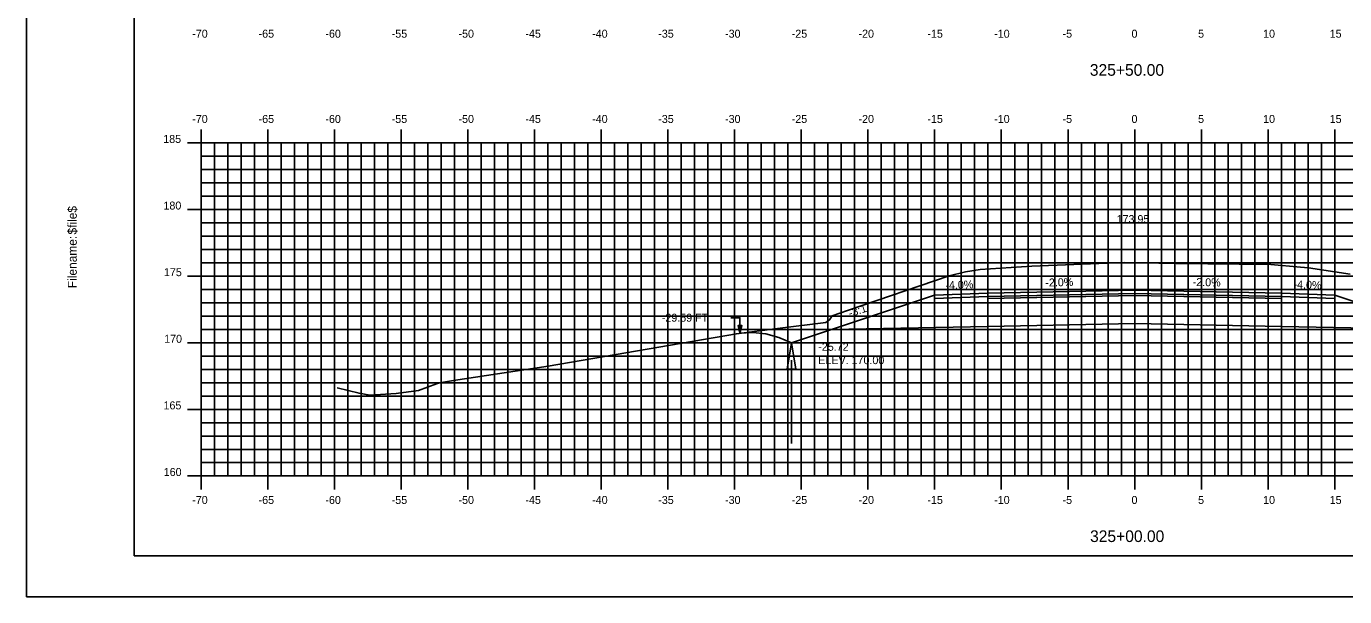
# Model space of a CAD drawing. Extents: x 1140537 to 1140707, y 608981 to 609091.
# Drawn here: x 1140537.2 to 1140636, y 608981.3 to 609024.1 of the extents above; entities that cross this region are included whole.
import ezdxf

# ---------------------------------------------------------------- set-up
doc = ezdxf.new("R2010")
doc.units = 0
for name, color, linetype in [('ANNOTATION', 7, 'Continuous'), ('BORDER', 7, 'Continuous'), ('D_Drainage_Ditch_Line', 7, 'Continuous'), ('D_Roadway_Centerline', 7, 'Continuous'), ('D_Roadway_Centerline_Text', 7, 'Continuous'), ('D_Roadway_Edge_Shoulder', 7, 'Continuous'), ('D_Roadway_Edge_TW', 7, 'Continuous'), ('D_Roadway_Pavement', 7, 'Continuous'), ('D_Roadway_SlopeLines', 7, 'Continuous'), ('D_Roadway_SubGrade', 7, 'Continuous'), ('D_Text_Standard', 7, 'Continuous'), ('H_V ANNOTATION', 7, 'Continuous'), ('MAJOR', 7, 'Continuous'), ('MINOR', 7, 'Continuous'), ('PLOT BOUNDARY', 7, 'Continuous'), ('S_Roadway_Centerline', 7, 'Continuous')]:
    doc.layers.add(name, color=color, linetype=linetype)

msp = doc.modelspace()

# ---------------------------------------------------------------- linework, layer by layer
msp.add_lwpolyline([(1140590.652, 609001.047), (1140591.619, 609001.097), (1140592.586, 609000.995), (1140593.553, 609000.74), (1140594.52, 609000.333), (1140597.52, 609001.333), (1140605.244, 609003.907), (1140605.245, 609003.907), (1140609.245, 609004.067), (1140620.245, 609004.287), (1140631.245, 609004.067), (1140635.245, 609003.907), (1140642.968, 609001.333), (1140645.968, 609000.333), (1140654.069, 609004.383), (1140655.319, 609004.932), (1140656.569, 609005.328), (1140657.819, 609005.571), (1140659.069, 609005.661)])
at = {"layer": 'BORDER'}
msp.add_lwpolyline([(1140545.245, 608984.335), (1140705.245, 608984.335), (1140705.245, 609089.335), (1140545.245, 609089.335)], close=True, dxfattribs=at)
at = {"layer": 'D_Drainage_Ditch_Line'}
msp.add_line((1140594.52, 608999.021), (1140594.52, 608992.777), dxfattribs=at)
msp.add_lwpolyline([(1140594.848, 608998.364), (1140594.192, 608998.364), (1140594.52, 609000.333)], close=True, dxfattribs=at)
at = {"layer": 'D_Roadway_Edge_Shoulder'}
for points in [[(1140609.245, 609004.067), (1140605.245, 609003.907), (1140605.245, 609003.657), (1140609.245, 609003.817)], [(1140631.245, 609004.067), (1140635.245, 609003.907), (1140635.245, 609003.657), (1140631.245, 609003.817)]]:
    msp.add_lwpolyline(points, close=True, dxfattribs=at)
at = {"layer": 'D_Roadway_Edge_TW'}
msp.add_lwpolyline([(1140609.245, 609003.817), (1140609.245, 609004.067), (1140620.245, 609004.287), (1140631.245, 609004.067), (1140631.245, 609003.817), (1140620.245, 609004.037)], close=True, dxfattribs=at)
at = {"layer": 'D_Roadway_Pavement'}
msp.add_lwpolyline([(1140609.245, 609003.651), (1140609.245, 609003.817), (1140620.245, 609004.037), (1140631.245, 609003.817), (1140631.245, 609003.651), (1140620.245, 609003.871)], close=True, dxfattribs=at)
at = {"layer": 'D_Roadway_SlopeLines'}
for points in [[(1140594.52, 609000.333), (1140593.553, 609000.74), (1140592.586, 609000.995), (1140591.619, 609001.097), (1140590.652, 609001.047)], [(1140597.52, 609001.333), (1140594.52, 609000.333)]]:
    msp.add_lwpolyline(points, dxfattribs=at)
at = {"layer": 'D_Roadway_SubGrade'}
for points in [[(1140609.245, 609003.651), (1140609.245, 609003.817), (1140605.245, 609003.657), (1140605.245, 609003.907), (1140605.244, 609003.907), (1140597.52, 609001.333), (1140609.245, 609001.567)], [(1140609.245, 609001.567), (1140609.245, 609003.651), (1140620.245, 609003.871), (1140631.245, 609003.651), (1140631.245, 609001.567), (1140620.245, 609001.787)], [(1140631.245, 609003.651), (1140631.245, 609003.817), (1140635.245, 609003.657), (1140635.245, 609003.907), (1140635.245, 609003.907), (1140642.968, 609001.333), (1140631.245, 609001.567)]]:
    msp.add_lwpolyline(points, close=True, dxfattribs=at)
at = {"layer": 'D_Text_Standard'}
msp.add_lwpolyline([(1140590.652, 609001.047), (1140590.648, 609002.216), (1140589.968, 609002.216)], dxfattribs=at)
msp.add_lwpolyline([(1140590.652, 609001.047), (1140590.504, 609001.628), (1140590.796, 609001.629)], close=True, dxfattribs=at)
at = {"layer": 'MAJOR'}
for p, q in [((1140550.245, 609016.337), (1140550.245, 609015.335)), ((1140555.245, 609016.337), (1140555.245, 609015.335)), ((1140560.245, 609016.337), (1140560.245, 609015.335)), ((1140565.245, 609016.337), (1140565.245, 609015.335)), ((1140570.245, 609016.337), (1140570.245, 609015.335)), ((1140575.245, 609016.337), (1140575.245, 609015.335)), ((1140580.245, 609016.337), (1140580.245, 609015.335)), ((1140585.245, 609016.337), (1140585.245, 609015.335)), ((1140590.245, 609016.337), (1140590.245, 609015.335)), ((1140595.245, 609016.337), (1140595.245, 609015.335)), ((1140600.245, 609016.337), (1140600.245, 609015.335)), ((1140605.245, 609016.337), (1140605.245, 609015.335)), ((1140610.245, 609016.337), (1140610.245, 609015.335)), ((1140615.245, 609016.337), (1140615.245, 609015.335)), ((1140620.245, 609016.337), (1140620.245, 609015.335)), ((1140625.245, 609016.337), (1140625.245, 609015.335)), ((1140630.245, 609016.337), (1140630.245, 609015.335)), ((1140635.245, 609016.337), (1140635.245, 609015.335)), ((1140549.243, 609015.335), (1140550.245, 609015.335)), ((1140550.245, 609015.335), (1140690.245, 609015.335)), ((1140550.245, 608990.335), (1140550.245, 609015.335)), ((1140550.245, 608990.335), (1140550.245, 609015.335)), ((1140550.245, 609015.335), (1140690.245, 609015.335)), ((1140555.245, 608990.335), (1140555.245, 609015.335)), ((1140560.245, 608990.335), (1140560.245, 609015.335)), ((1140565.245, 608990.335), (1140565.245, 609015.335)), ((1140570.245, 608990.335), (1140570.245, 609015.335)), ((1140575.245, 608990.335), (1140575.245, 609015.335)), ((1140580.245, 608990.335), (1140580.245, 609015.335)), ((1140585.245, 608990.335), (1140585.245, 609015.335)), ((1140590.245, 608990.335), (1140590.245, 609015.335)), ((1140595.245, 608990.335), (1140595.245, 609015.335)), ((1140600.245, 608990.335), (1140600.245, 609015.335)), ((1140605.245, 608990.335), (1140605.245, 609015.335)), ((1140610.245, 608990.335), (1140610.245, 609015.335)), ((1140615.245, 608990.335), (1140615.245, 609015.335)), ((1140620.245, 608990.335), (1140620.245, 609015.335)), ((1140625.245, 608990.335), (1140625.245, 609015.335)), ((1140630.245, 608990.335), (1140630.245, 609015.335)), ((1140635.245, 608990.335), (1140635.245, 609015.335)), ((1140549.243, 609010.335), (1140550.245, 609010.335)), ((1140550.245, 609010.335), (1140690.245, 609010.335)), ((1140549.243, 609005.335), (1140550.245, 609005.335)), ((1140550.245, 609005.335), (1140690.245, 609005.335)), ((1140549.243, 609000.335), (1140550.245, 609000.335)), ((1140550.245, 609000.335), (1140690.245, 609000.335)), ((1140549.243, 608995.335), (1140550.245, 608995.335)), ((1140550.245, 608995.335), (1140690.245, 608995.335)), ((1140549.243, 608990.335), (1140550.245, 608990.335)), ((1140550.245, 608990.335), (1140690.245, 608990.335)), ((1140550.245, 608990.335), (1140690.245, 608990.335)), ((1140550.245, 608989.333), (1140550.245, 608990.335)), ((1140555.245, 608989.333), (1140555.245, 608990.335)), ((1140560.245, 608989.333), (1140560.245, 608990.335)), ((1140565.245, 608989.333), (1140565.245, 608990.335)), ((1140570.245, 608989.333), (1140570.245, 608990.335)), ((1140575.245, 608989.333), (1140575.245, 608990.335)), ((1140580.245, 608989.333), (1140580.245, 608990.335)), ((1140585.245, 608989.333), (1140585.245, 608990.335)), ((1140590.245, 608989.333), (1140590.245, 608990.335)), ((1140595.245, 608989.333), (1140595.245, 608990.335)), ((1140600.245, 608989.333), (1140600.245, 608990.335)), ((1140605.245, 608989.333), (1140605.245, 608990.335)), ((1140610.245, 608989.333), (1140610.245, 608990.335)), ((1140615.245, 608989.333), (1140615.245, 608990.335)), ((1140620.245, 608989.333), (1140620.245, 608990.335)), ((1140625.245, 608989.333), (1140625.245, 608990.335)), ((1140630.245, 608989.333), (1140630.245, 608990.335)), ((1140635.245, 608989.333), (1140635.245, 608990.335))]:
    msp.add_line(p, q, dxfattribs=at)
at = {"layer": 'MINOR'}
for p, q in [((1140551.245, 608990.335), (1140551.245, 609015.335)), ((1140552.245, 608990.335), (1140552.245, 609015.335)), ((1140553.245, 608990.335), (1140553.245, 609015.335)), ((1140554.245, 608990.335), (1140554.245, 609015.335)), ((1140556.245, 608990.335), (1140556.245, 609015.335)), ((1140557.245, 608990.335), (1140557.245, 609015.335)), ((1140558.245, 608990.335), (1140558.245, 609015.335)), ((1140559.245, 608990.335), (1140559.245, 609015.335)), ((1140561.245, 608990.335), (1140561.245, 609015.335)), ((1140562.245, 608990.335), (1140562.245, 609015.335)), ((1140563.245, 608990.335), (1140563.245, 609015.335)), ((1140564.245, 608990.335), (1140564.245, 609015.335)), ((1140566.245, 608990.335), (1140566.245, 609015.335)), ((1140567.245, 608990.335), (1140567.245, 609015.335)), ((1140568.245, 608990.335), (1140568.245, 609015.335)), ((1140569.245, 608990.335), (1140569.245, 609015.335)), ((1140571.245, 608990.335), (1140571.245, 609015.335)), ((1140572.245, 608990.335), (1140572.245, 609015.335)), ((1140573.245, 608990.335), (1140573.245, 609015.335)), ((1140574.245, 608990.335), (1140574.245, 609015.335)), ((1140576.245, 608990.335), (1140576.245, 609015.335)), ((1140577.245, 608990.335), (1140577.245, 609015.335)), ((1140578.245, 608990.335), (1140578.245, 609015.335)), ((1140579.245, 608990.335), (1140579.245, 609015.335)), ((1140581.245, 608990.335), (1140581.245, 609015.335)), ((1140582.245, 608990.335), (1140582.245, 609015.335)), ((1140583.245, 608990.335), (1140583.245, 609015.335)), ((1140584.245, 608990.335), (1140584.245, 609015.335)), ((1140586.245, 608990.335), (1140586.245, 609015.335)), ((1140587.245, 608990.335), (1140587.245, 609015.335)), ((1140588.245, 608990.335), (1140588.245, 609015.335)), ((1140589.245, 608990.335), (1140589.245, 609015.335)), ((1140591.245, 608990.335), (1140591.245, 609015.335)), ((1140592.245, 608990.335), (1140592.245, 609015.335)), ((1140593.245, 608990.335), (1140593.245, 609015.335)), ((1140594.245, 608990.335), (1140594.245, 609015.335)), ((1140596.245, 608990.335), (1140596.245, 609015.335)), ((1140597.245, 608990.335), (1140597.245, 609015.335)), ((1140598.245, 608990.335), (1140598.245, 609015.335)), ((1140599.245, 608990.335), (1140599.245, 609015.335)), ((1140601.245, 608990.335), (1140601.245, 609015.335)), ((1140602.245, 608990.335), (1140602.245, 609015.335)), ((1140603.245, 608990.335), (1140603.245, 609015.335)), ((1140604.245, 608990.335), (1140604.245, 609015.335)), ((1140606.245, 608990.335), (1140606.245, 609015.335)), ((1140607.245, 608990.335), (1140607.245, 609015.335)), ((1140608.245, 608990.335), (1140608.245, 609015.335)), ((1140609.245, 608990.335), (1140609.245, 609015.335)), ((1140611.245, 608990.335), (1140611.245, 609015.335)), ((1140612.245, 608990.335), (1140612.245, 609015.335)), ((1140613.245, 608990.335), (1140613.245, 609015.335)), ((1140614.245, 608990.335), (1140614.245, 609015.335)), ((1140616.245, 608990.335), (1140616.245, 609015.335)), ((1140617.245, 608990.335), (1140617.245, 609015.335)), ((1140618.245, 608990.335), (1140618.245, 609015.335)), ((1140619.245, 608990.335), (1140619.245, 609015.335)), ((1140621.245, 608990.335), (1140621.245, 609015.335)), ((1140622.245, 608990.335), (1140622.245, 609015.335)), ((1140623.245, 608990.335), (1140623.245, 609015.335)), ((1140624.245, 608990.335), (1140624.245, 609015.335)), ((1140626.245, 608990.335), (1140626.245, 609015.335)), ((1140627.245, 608990.335), (1140627.245, 609015.335)), ((1140628.245, 608990.335), (1140628.245, 609015.335)), ((1140629.245, 608990.335), (1140629.245, 609015.335)), ((1140631.245, 608990.335), (1140631.245, 609015.335)), ((1140632.245, 608990.335), (1140632.245, 609015.335)), ((1140633.245, 608990.335), (1140633.245, 609015.335)), ((1140634.245, 608990.335), (1140634.245, 609015.335)), ((1140550.245, 609014.335), (1140690.245, 609014.335)), ((1140550.245, 609014.335), (1140551.247, 609014.335)), ((1140550.245, 609013.335), (1140690.245, 609013.335)), ((1140550.245, 609013.335), (1140551.247, 609013.335)), ((1140550.245, 609012.335), (1140690.245, 609012.335)), ((1140550.245, 609012.335), (1140551.247, 609012.335)), ((1140550.245, 609011.335), (1140690.245, 609011.335)), ((1140550.245, 609011.335), (1140551.247, 609011.335)), ((1140550.245, 609009.335), (1140690.245, 609009.335)), ((1140550.245, 609009.335), (1140551.247, 609009.335)), ((1140550.245, 609008.335), (1140690.245, 609008.335)), ((1140550.245, 609008.335), (1140551.247, 609008.335)), ((1140550.245, 609007.335), (1140690.245, 609007.335)), ((1140550.245, 609007.335), (1140551.247, 609007.335)), ((1140550.245, 609006.335), (1140690.245, 609006.335)), ((1140550.245, 609006.335), (1140551.247, 609006.335)), ((1140550.245, 609004.335), (1140690.245, 609004.335)), ((1140550.245, 609004.335), (1140551.247, 609004.335)), ((1140550.245, 609003.335), (1140690.245, 609003.335)), ((1140550.245, 609003.335), (1140551.247, 609003.335)), ((1140550.245, 609002.335), (1140690.245, 609002.335)), ((1140550.245, 609002.335), (1140551.247, 609002.335)), ((1140550.245, 609001.335), (1140690.245, 609001.335)), ((1140550.245, 609001.335), (1140551.247, 609001.335)), ((1140550.245, 608999.335), (1140690.245, 608999.335)), ((1140550.245, 608999.335), (1140551.247, 608999.335)), ((1140550.245, 608998.335), (1140690.245, 608998.335)), ((1140550.245, 608998.335), (1140551.247, 608998.335)), ((1140550.245, 608997.335), (1140690.245, 608997.335)), ((1140550.245, 608997.335), (1140551.247, 608997.335)), ((1140550.245, 608996.335), (1140690.245, 608996.335)), ((1140550.245, 608996.335), (1140551.247, 608996.335)), ((1140550.245, 608994.335), (1140690.245, 608994.335)), ((1140550.245, 608994.335), (1140551.247, 608994.335)), ((1140550.245, 608993.335), (1140690.245, 608993.335)), ((1140550.245, 608993.335), (1140551.247, 608993.335)), ((1140550.245, 608992.335), (1140690.245, 608992.335)), ((1140550.245, 608992.335), (1140551.247, 608992.335)), ((1140550.245, 608991.335), (1140690.245, 608991.335)), ((1140550.245, 608991.335), (1140551.247, 608991.335))]:
    msp.add_line(p, q, dxfattribs=at)
at = {"layer": 'PLOT BOUNDARY'}
msp.add_lwpolyline([(1140537.151, 608981.276), (1140707.151, 608981.276), (1140707.151, 609091.276), (1140537.151, 609091.276)], close=True, dxfattribs=at)
at = {"layer": 'S_Roadway_Centerline'}
msp.add_lwpolyline([(1140560.445, 608996.953), (1140562.096, 608996.55), (1140562.911, 608996.409), (1140564.877, 608996.526), (1140566.549, 608996.741), (1140567.911, 608997.253), (1140568.116, 608997.339), (1140569.162, 608997.501), (1140576.263, 608998.591), (1140590.387, 609001.012), (1140593.462, 609001.414), (1140597.095, 609001.866), (1140597.36, 609002.059), (1140597.575, 609002.348), (1140598.706, 609002.746), (1140606.337, 609005.372), (1140607.571, 609005.662), (1140608.651, 609005.84), (1140612.531, 609006.079), (1140619.457, 609006.365), (1140623.345, 609006.285), (1140630.459, 609006.21), (1140632.674, 609006.004), (1140633.281, 609005.962), (1140636.4, 609005.487)], dxfattribs=at)

# ---------------------------------------------------------------- texts
at = {"layer": 'ANNOTATION'}
for s, rotation, p in [('-4.0%', 2.29061, (1140606.06, 609004.341)), ('-2.0%', 1.14576, (1140613.548, 609004.554)), ('-2.0%', 358.85424, (1140624.588, 609004.601)), ('-4.0%', 357.70939, (1140632.14, 609004.432)), ('-3:1', 18.43482, (1140598.899, 609002.247))]:
    msp.add_text(s, height=0.6, rotation=rotation, dxfattribs=at).set_placement(p)
at = {"layer": 'BORDER'}
for s, p in [('$file$', (1140540.93, 609008.461)), ('Filename:', (1140540.93, 609004.433))]:
    msp.add_text(s, height=0.6696, rotation=90, dxfattribs=at).set_placement(p)
at = {"layer": 'D_Roadway_Centerline'}
for s, p in [('C', (1140620.239, 609004.287)), ('L', (1140620.245, 609004.28))]:
    msp.add_text(s, height=0.0146, dxfattribs=at).set_placement(p)
at = {"layer": 'D_Roadway_Centerline_Text'}
msp.add_text('173.95', height=0.6, dxfattribs=at).set_placement((1140618.888, 609009.319))
at = {"layer": 'D_Text_Standard'}
for s, p in [('-29.59 FT', (1140584.791, 609001.916)), ('-25.72', (1140596.52, 608999.733)), ('ELEV. 170.00', (1140596.52, 608998.731))]:
    msp.add_text(s, height=0.6, dxfattribs=at).set_placement(p)
at = {"layer": 'H_V ANNOTATION'}
for s, height, p in [('-70', 0.6, (1140549.586, 609023.235)), ('-65', 0.6, (1140554.562, 609023.235)), ('-60', 0.6, (1140559.57, 609023.235)), ('-55', 0.6, (1140564.541, 609023.235)), ('-50', 0.6, (1140569.549, 609023.235)), ('-45', 0.6, (1140574.562, 609023.235)), ('-40', 0.6, (1140579.57, 609023.235)), ('-35', 0.6, (1140584.525, 609023.235)), ('-30', 0.6, (1140589.533, 609023.235)), ('-25', 0.6, (1140594.53, 609023.235)), ('-20', 0.6, (1140599.538, 609023.235)), ('-15', 0.6, (1140604.701, 609023.235)), ('-10', 0.6, (1140609.709, 609023.235)), ('-5', 0.6, (1140614.835, 609023.235)), ('0', 0.6, (1140620.004, 609023.235)), ('5', 0.6, (1140624.996, 609023.235)), ('10', 0.6, (1140629.87, 609023.235)), ('15', 0.6, (1140634.862, 609023.235)), ('325+50.00', 0.875, (1140616.881, 609020.378)), ('-70', 0.6, (1140549.586, 609016.835)), ('-65', 0.6, (1140554.562, 609016.835)), ('-60', 0.6, (1140559.57, 609016.835)), ('-55', 0.6, (1140564.541, 609016.835)), ('-50', 0.6, (1140569.549, 609016.835)), ('-45', 0.6, (1140574.562, 609016.835)), ('-40', 0.6, (1140579.57, 609016.835)), ('-35', 0.6, (1140584.525, 609016.835)), ('-30', 0.6, (1140589.533, 609016.835)), ('-25', 0.6, (1140594.53, 609016.835)), ('-20', 0.6, (1140599.538, 609016.835)), ('-15', 0.6, (1140604.701, 609016.835)), ('-10', 0.6, (1140609.709, 609016.835)), ('-5', 0.6, (1140614.835, 609016.835)), ('0', 0.6, (1140620.004, 609016.835)), ('5', 0.6, (1140624.996, 609016.835)), ('10', 0.6, (1140629.87, 609016.835)), ('15', 0.6, (1140634.862, 609016.835)), ('185', 0.6, (1140547.412, 609015.335)), ('180', 0.6, (1140547.428, 609010.335)), ('175', 0.6, (1140547.465, 609005.335)), ('170', 0.6, (1140547.481, 609000.335)), ('165', 0.6, (1140547.433, 608995.335)), ('160', 0.6, (1140547.449, 608990.335)), ('-70', 0.6, (1140549.586, 608988.235)), ('-65', 0.6, (1140554.562, 608988.235)), ('-60', 0.6, (1140559.57, 608988.235)), ('-55', 0.6, (1140564.541, 608988.235)), ('-50', 0.6, (1140569.549, 608988.235)), ('-45', 0.6, (1140574.562, 608988.235)), ('-40', 0.6, (1140579.57, 608988.235)), ('-35', 0.6, (1140584.525, 608988.235)), ('-30', 0.6, (1140589.533, 608988.235)), ('-25', 0.6, (1140594.53, 608988.235)), ('-20', 0.6, (1140599.538, 608988.235)), ('-15', 0.6, (1140604.701, 608988.235)), ('-10', 0.6, (1140609.709, 608988.235)), ('-5', 0.6, (1140614.835, 608988.235)), ('0', 0.6, (1140620.004, 608988.235)), ('5', 0.6, (1140624.996, 608988.235)), ('10', 0.6, (1140629.87, 608988.235)), ('15', 0.6, (1140634.862, 608988.235)), ('325+00.00', 0.875, (1140616.897, 608985.378))]:
    msp.add_text(s, height=height, dxfattribs=at).set_placement(p)
at = {"layer": 'MAJOR'}
msp.add_text('-', height=0.006, dxfattribs=at).set_placement((1140550.24, 608990.335))
at = {"layer": 'S_Roadway_Centerline'}
for s, p in [('L', (1140619.449, 609006.358)), ('C', (1140619.452, 609006.365))]:
    msp.add_text(s, height=0.0146, dxfattribs=at).set_placement(p)

doc.saveas('drawing.dxf')
